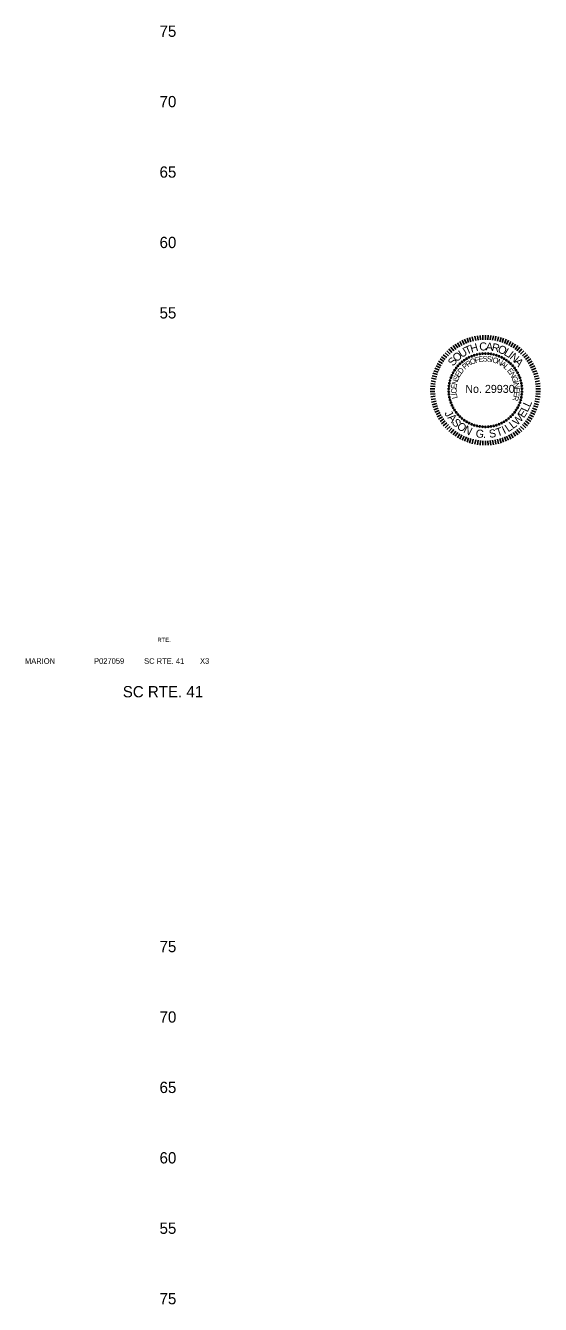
# Model space of a CAD drawing. Extents: x 952 to 1206, y 942 to 2399.
# Drawn here: x 1147.4 to 1184, y 1860 to 1950.8 of the extents above; entities that cross this region are included whole.
import ezdxf

# ---------------------------------------------------------------- set-up
doc = ezdxf.new("R2010")
doc.units = 0
for name, color, linetype in [('Default', 7, 'Continuous'), ('RD_SHT_TX', 7, 'Continuous'), ('RD_TX_PEShield', 7, 'Continuous'), ('RD_XS_TX_Elev_EX', 7, 'Continuous')]:
    doc.layers.add(name, color=color, linetype=linetype)

# ---------------------------------------------------------------- blocks, each defined once
blk = doc.blocks.new('STILLWELL')
at = {"layer": 'RD_TX_PEShield'}
for p, q in [((-10.28, 33.44), (-11.22, 36.57)), ((-8.61, 33.9), (-9.39, 37.07)), ((-6.92, 34.27), (-7.55, 37.48)), ((-5.21, 34.57), (-5.68, 37.8)), ((-3.49, 34.77), (-3.81, 38.03)), ((-1.76, 34.9), (-1.92, 38.16)), ((-0.03, 34.94), (-0.03, 38.21)), ((1.71, 34.9), (1.86, 38.16)), ((3.43, 34.77), (3.75, 38.03)), ((5.15, 34.57), (5.63, 37.8)), ((6.86, 34.27), (7.49, 37.48)), ((8.56, 33.9), (9.34, 37.07)), ((10.23, 33.44), (11.16, 36.57)), ((-23.81, 25.92), (-25.98, 28.37)), ((-22.49, 27.04), (-24.53, 29.59)), ((-21.11, 28.09), (-23.03, 30.73)), ((-19.68, 29.08), (-21.48, 31.81)), ((-18.21, 29.99), (-19.87, 32.81)), ((-16.7, 30.83), (-18.22, 33.73)), ((-15.14, 31.6), (-16.52, 34.56)), ((-13.55, 32.29), (-14.79, 35.32)), ((-11.93, 32.91), (-13.02, 35.99)), ((11.88, 32.91), (12.96, 35.99)), ((13.5, 32.29), (14.73, 35.32)), ((15.09, 31.6), (16.46, 34.56)), ((16.64, 30.83), (18.16, 33.73)), ((18.16, 29.99), (19.81, 32.81)), ((19.63, 29.08), (21.42, 31.81)), ((21.06, 28.09), (22.98, 30.73)), ((22.43, 27.04), (24.48, 29.59)), ((23.76, 25.92), (25.92, 28.37)), ((-30.5, 18), (-33.27, 19.72)), ((-29.55, 19.45), (-32.24, 21.3)), ((-28.53, 20.85), (-31.12, 22.83)), ((-27.44, 22.2), (-29.94, 24.31)), ((-26.29, 23.5), (-28.69, 25.72)), ((-25.08, 24.74), (-27.37, 27.08)), ((25.03, 24.74), (27.31, 27.08)), ((26.24, 23.5), (28.63, 25.72)), ((27.39, 22.2), (29.88, 24.31)), ((28.47, 20.85), (31.07, 22.83)), ((29.49, 19.45), (32.18, 21.3)), ((30.44, 18), (33.22, 19.72)), ((-34.64, 8.5), (-37.79, 9.35)), ((-34.14, 10.16), (-37.25, 11.17)), ((-33.57, 11.79), (-36.62, 12.95)), ((-32.91, 13.4), (-35.91, 14.7)), ((-32.18, 14.97), (-35.11, 16.42)), ((-31.38, 16.5), (-34.23, 18.09)), ((31.32, 16.5), (34.18, 18.09)), ((32.13, 14.97), (35.06, 16.42)), ((32.86, 13.4), (35.85, 14.7)), ((33.51, 11.79), (36.57, 12.95)), ((34.09, 10.16), (37.19, 11.17)), ((34.58, 8.5), (37.73, 9.35)), ((-35.89, -0.06), (-39.15, 0.02)), ((-35.8, 1.67), (-39.06, 1.91)), ((-35.64, 3.4), (-38.88, 3.79)), ((-35.39, 5.11), (-38.61, 5.66)), ((-35.05, 6.81), (-38.24, 7.52)), ((35, 6.81), (38.19, 7.52)), ((35.33, 5.11), (38.55, 5.66)), ((35.58, 3.4), (38.82, 3.79)), ((35.75, 1.67), (39.01, 1.91)), ((35.83, -0.06), (39.1, 0.02)), ((-35.89, -1.79), (-39.15, -1.87)), ((-35.8, -3.53), (-39.06, -3.76)), ((-35.64, -5.25), (-38.88, -5.65)), ((-35.39, -6.97), (-38.61, -7.52)), ((-35.05, -8.67), (-38.24, -9.37)), ((35, -8.67), (38.19, -9.37)), ((35.33, -6.97), (38.55, -7.52)), ((35.58, -5.25), (38.82, -5.65)), ((35.75, -3.53), (39.01, -3.76)), ((35.83, -1.79), (39.1, -1.87)), ((-34.64, -10.35), (-37.79, -11.21)), ((-34.14, -12.01), (-37.25, -13.02)), ((-33.57, -13.65), (-36.62, -14.81)), ((-32.91, -15.25), (-35.91, -16.56)), ((-32.18, -16.83), (-35.11, -18.27)), ((32.13, -16.83), (35.06, -18.27)), ((32.86, -15.25), (35.85, -16.56)), ((33.51, -13.65), (36.57, -14.81)), ((34.09, -12.01), (37.19, -13.02)), ((34.58, -10.35), (37.73, -11.21)), ((-31.38, -18.36), (-34.23, -19.95)), ((-30.5, -19.85), (-33.27, -21.58)), ((-29.55, -21.3), (-32.24, -23.16)), ((-28.53, -22.71), (-31.12, -24.69)), ((-27.44, -24.06), (-29.94, -26.16)), ((-26.29, -25.36), (-28.69, -27.58)), ((-25.08, -26.6), (-27.37, -28.93)), ((25.03, -26.6), (27.31, -28.93)), ((26.24, -25.36), (28.63, -27.58)), ((27.39, -24.06), (29.88, -26.16)), ((28.47, -22.71), (31.07, -24.69)), ((29.49, -21.3), (32.18, -23.16)), ((30.44, -19.85), (33.22, -21.58)), ((31.32, -18.36), (34.18, -19.95)), ((-23.81, -27.78), (-25.98, -30.22)), ((-22.49, -28.89), (-24.53, -31.44)), ((-21.11, -29.95), (-23.03, -32.59)), ((-19.68, -30.93), (-21.48, -33.66)), ((-18.21, -31.85), (-19.87, -34.66)), ((-16.7, -32.69), (-18.22, -35.58)), ((-15.14, -33.46), (-16.52, -36.42)), ((-13.55, -34.15), (-14.79, -37.18)), ((-11.93, -34.76), (-13.02, -37.85)), ((-10.28, -35.3), (-11.22, -38.43)), ((-8.61, -35.76), (-9.39, -38.93)), ((-6.92, -36.13), (-7.55, -39.34)), ((6.86, -36.13), (7.49, -39.34)), ((8.56, -35.76), (9.34, -38.93)), ((10.23, -35.3), (11.16, -38.43)), ((11.88, -34.76), (12.96, -37.85)), ((13.5, -34.15), (14.73, -37.18)), ((15.09, -33.46), (16.46, -36.42)), ((16.64, -32.69), (18.16, -35.58)), ((18.16, -31.85), (19.81, -34.66)), ((19.63, -30.93), (21.42, -33.66)), ((21.06, -29.95), (22.98, -32.59)), ((22.43, -28.89), (24.48, -31.44)), ((23.76, -27.78), (25.92, -30.22)), ((-5.21, -36.42), (-5.68, -39.65)), ((-3.49, -36.63), (-3.81, -39.88)), ((-1.76, -36.76), (-1.92, -40.02)), ((-0.03, -36.8), (-0.03, -40.06)), ((1.71, -36.76), (1.86, -40.02)), ((3.43, -36.63), (3.75, -39.88)), ((5.15, -36.42), (5.63, -39.65))]:
    blk.add_line(p, q, dxfattribs=at)
for centre in [(-18.09, 17.84), (-16.6, 19.17), (-15.01, 20.38), (-13.34, 21.46), (-11.59, 22.41), (-9.76, 23.23), (-7.89, 23.9), (-5.96, 24.43), (-4, 24.81), (-2.02, 25.04), (-0.03, 25.12), (1.97, 25.04), (3.95, 24.81), (5.91, 24.43), (7.83, 23.9), (9.71, 23.23), (11.53, 22.41), (13.28, 21.46), (14.96, 20.38), (16.54, 19.17), (18.03, 17.84), (-23.79, 9.73), (-22.91, 11.51), (-21.89, 13.23), (-20.74, 14.86), (-19.47, 16.4), (19.42, 16.4), (20.69, 14.86), (21.83, 13.23), (22.85, 11.51), (23.74, 9.73), (-26.05, 0.07), (-25.9, 2.06), (-25.6, 4.03), (-25.14, 5.97), (-24.54, 7.88), (24.48, 7.88), (25.09, 5.97), (25.54, 4.03), (25.85, 2.06), (26, 0.07), (-26.05, -1.93), (-25.9, -3.92), (-25.6, -5.89), (-25.14, -7.83), (25.09, -7.83), (25.54, -5.89), (25.85, -3.92), (26, -1.93), (-24.54, -9.73), (-23.79, -11.58), (-22.91, -13.37), (-21.89, -15.09), (-20.74, -16.72), (-19.47, -18.26), (19.42, -18.26), (20.69, -16.72), (21.83, -15.09), (22.85, -13.37), (23.74, -11.58), (24.48, -9.73), (-18.09, -19.69), (-16.6, -21.02), (-15.01, -22.23), (-13.34, -23.32), (-11.59, -24.27), (-9.76, -25.09), (-7.89, -25.76), (-5.96, -26.29), (-4, -26.67), (-2.02, -26.9), (-0.03, -26.97), (1.97, -26.9), (3.95, -26.67), (5.91, -26.29), (7.83, -25.76), (9.71, -25.09), (11.53, -24.27), (13.28, -23.32), (14.96, -22.23), (16.54, -21.02), (18.03, -19.69)]:
    blk.add_circle(centre, 0.49, dxfattribs=at)
for s, height, rotation, p in [('U', 5.68, 32.21524, (-16.89, 21.85)), ('T', 5.68, 23.50438, (-13.24, 24.14)), ('H', 5.68, 16.13567, (-9.92, 25.63)), ('C', 5.68, 4.07599, (-4.15, 27.11)), ('A', 5.68, 355.36513, (0.14, 27.41)), ('R', 5.68, 347.31877, (4.1, 27.11)), ('O', 5.68, 338.6079, (8.3, 26.16)), ('L', 5.68, 329.22596, (12.61, 24.44)), ('S', 5.68, 49.64355, (-22.94, 15.75)), ('O', 5.68, 41.59718, (-20.38, 18.79)), ('R', 3.92, 33.30566, (-12.46, 15.32)), ('O', 3.92, 24.97351, (-9.98, 16.95)), ('F', 3.92, 15.99945, (-7.07, 18.28)), ('E', 3.92, 8.95111, (-4.65, 19)), ('S', 3.92, 1.25456, (-1.94, 19.44)), ('S', 3.92, 353.55802, (0.8, 19.51)), ('I', 3.92, 345.86148, (3.53, 19.22)), ('O', 3.92, 342.65826, (4.65, 18.99)), ('N', 3.92, 333.6842, (7.7, 18.01)), ('A', 3.92, 325.35205, (10.36, 16.69)), ('I', 5.68, 322.52176, (15.48, 22.79)), ('N', 5.68, 319.17294, (16.84, 21.84)), ('A', 5.68, 310.46208, (20.09, 19.02)), ('S', 3.92, 67.93066, (-19.49, 5.38)), ('E', 3.92, 60.23412, (-18.47, 7.93)), ('D', 3.92, 52.53758, (-17.12, 10.32)), ('P', 3.92, 41.0022, (-14.52, 13.51)), ('L', 3.92, 317.65551, (12.63, 15.14)), ('E', 3.92, 308.03955, (15.14, 12.8)), ('N', 3.92, 300.34301, (16.84, 10.65)), ('C', 3.92, 92.29151, (-20.36, -3.21)), ('E', 3.92, 83.95936, (-20.47, -0.24)), ('N', 3.92, 76.26281, (-20.2, 2.49)), ('G', 3.92, 292.01086, (18.34, 8.08)), ('I', 3.92, 283.0368, (19.52, 5.11)), ('N', 3.92, 279.83358, (19.83, 4.01)), ('E', 3.92, 271.50143, (20.33, 1.08)), ('I', 3.92, 95.49473, (-20.2, -4.35)), ('L', 3.92, 101.90747, (-19.69, -6.58)), ('R', 3.92, 256.10834, (20.13, -4.4)), ('E', 3.92, 263.80489, (20.42, -1.67)), ('J', 5.68, 299.03302, (-29.35, -17.26)), ('W', 5.68, 47.05177, (22.62, -26.41)), ('E', 5.68, 56.4327, (27.3, -21.12)), ('L', 5.68, 65.09801, (29.98, -16.89)), ('L', 5.68, 65.09801, (31.58, -13.34)), ('A', 5.68, 310.58873, (-27.19, -20.61)), ('S', 5.68, 310.58873, (-24.3, -23.99)), ('O', 5.68, 321.00719, (-20.82, -27.39)), ('N', 5.68, 333.43256, (-16.05, -30.75)), ('T', 5.68, 18.90189, (8.5, -33.88)), ('I', 5.68, 25.39911, (13.3, -32.17)), ('L', 5.68, 34.06442, (16.21, -30.92)), ('L', 5.68, 37.67084, (19.57, -28.72)), ('G', 5.68, 352.2045, (-7.22, -34.2)), ('.', 5.68, 0.86982, (-1.8, -34.9)), ('S', 5.68, 8.08265, (2.93, -34.79))]:
    blk.add_text(s, height=height, rotation=rotation, dxfattribs=at).set_placement(p)
blk.add_text('No. 29930', height=5.685, dxfattribs=at).set_placement((-14.3, -2.84))

msp = doc.modelspace()

# ---------------------------------------------------------------- block references
at = {"layer": 'Default', "xscale": 0.1, "yscale": 0.10000000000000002}
msp.add_blockref('STILLWELL', (1180.075, 1925), dxfattribs=at)

# ---------------------------------------------------------------- texts
at = {"layer": 'RD_SHT_TX'}
for s, height, p in [('RTE.', 0.3, (1156.77, 1907.03)), ('MARION', 0.4, (1147.353, 1905.476)), ('P027059', 0.4, (1152.265, 1905.476)), ('SC RTE. 41', 0.4, (1155.822, 1905.476)), ('X3', 0.4, (1159.795, 1905.476)), ('SC RTE. 41', 0.8, (1154.307, 1903.098))]:
    msp.add_text(s, height=height, dxfattribs=at).set_placement(p)
at = {"layer": 'RD_XS_TX_Elev_EX'}
for s, p in [('75', (1156.919, 1950)), ('70', (1156.919, 1945)), ('65', (1156.919, 1940)), ('60', (1156.919, 1935)), ('55', (1156.919, 1930)), ('75', (1156.919, 1885)), ('70', (1156.919, 1880)), ('65', (1156.919, 1875)), ('60', (1156.919, 1870)), ('55', (1156.919, 1865)), ('75', (1156.919, 1860))]:
    msp.add_text(s, height=0.8, dxfattribs=at).set_placement(p)

doc.saveas('drawing.dxf')
